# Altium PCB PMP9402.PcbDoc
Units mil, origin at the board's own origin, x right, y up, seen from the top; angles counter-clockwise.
Board outline 2250.03 x 802.03 mil, 2 copper layers (Top Layer, Bottom Layer), stack 62 mil thick; 47 components, 26 nets, 144 pads, 123 vias.
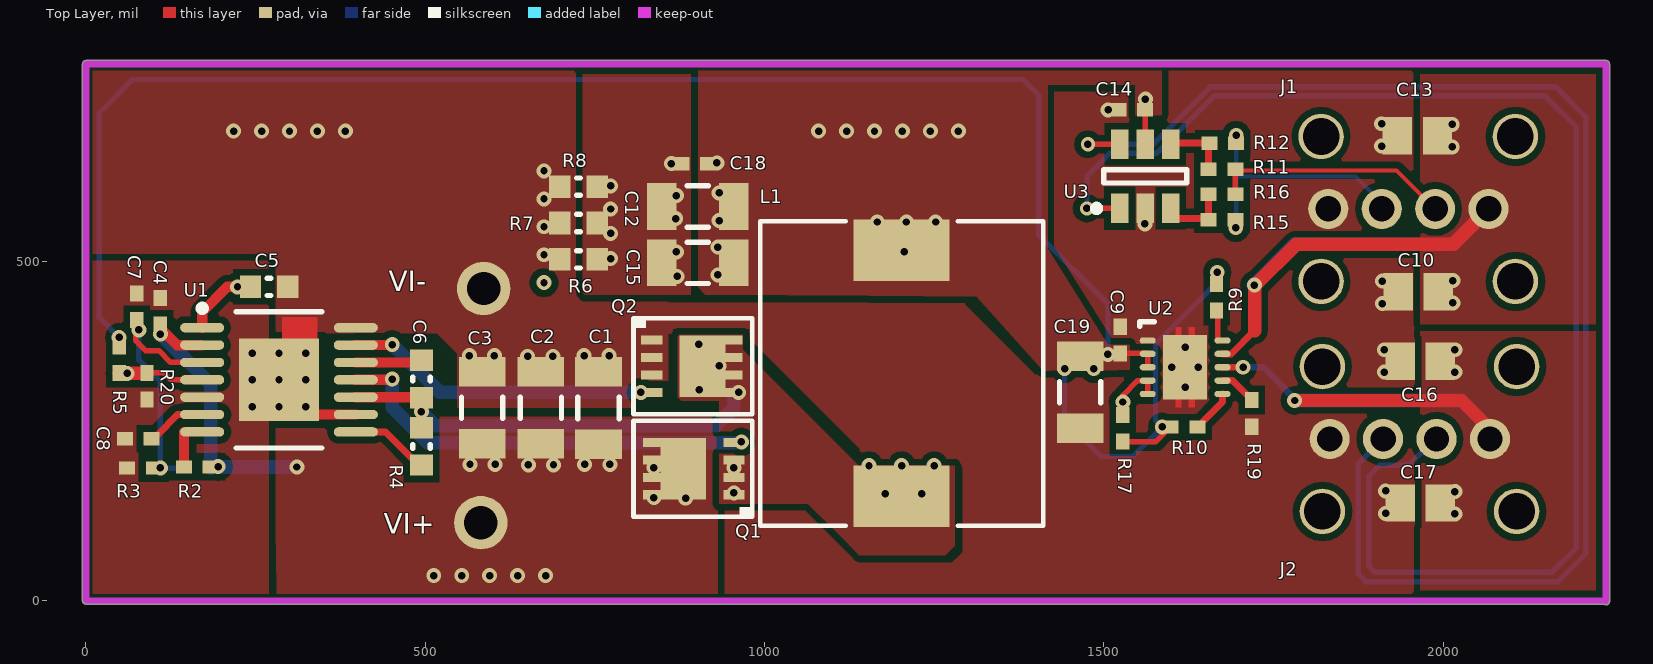
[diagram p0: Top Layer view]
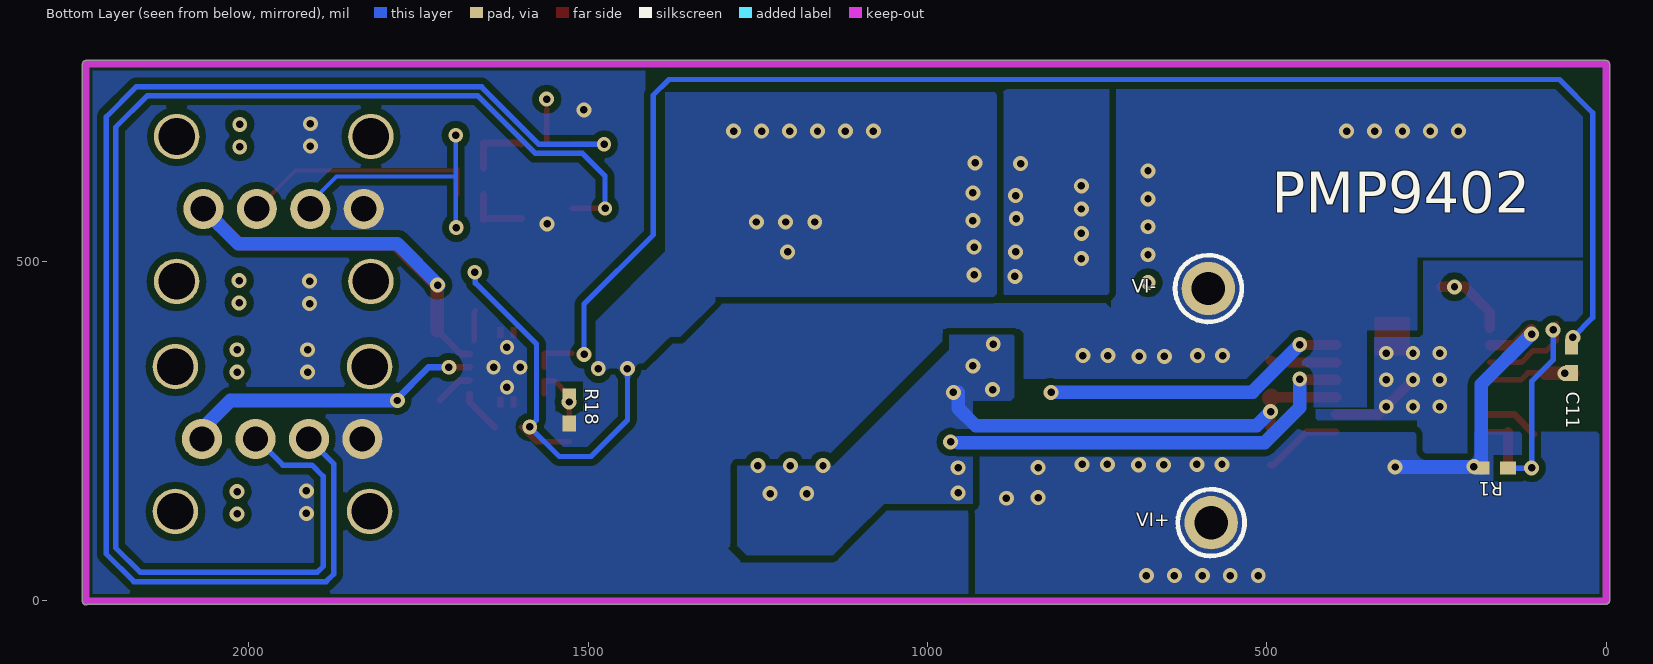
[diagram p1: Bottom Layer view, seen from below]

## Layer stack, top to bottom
Top Solder: solder mask 0.4, Solder Resist, Dk 3.5
Top Layer: signal copper 1.4
Dielectric1: core 59.2, FR-4, Dk 4.8
Bottom Layer: signal copper 1.4
Bottom Solder: solder mask 0.4, Solder Resist, Dk 3.5

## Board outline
0,-5.02 cw(c0,0) -5.01,0 -5.01,791 cw(c0,791) 0,796.01 2240,796.01 cw(c2240,791) 2245.02,791 cw(c2240,791) 2244.99,790.5 cw(c2240,790) 2245.02,790 2245.02,-1 cw(c2240,-1) 2236.99,-5.02

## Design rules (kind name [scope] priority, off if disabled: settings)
AcuteAngle [All] p1: minimum=4.50000000000000E+0001 checktracksonly=FALSE
AssemblyTestPointUsage [All] p1: valid=2
Clearance Clearance_BoardEdge_MountingHoles [OnCopper and InComponentClass('Mounting Holes') vs IsKeepOut] p1: gap=10
Clearance Clearance_BoardEdge_Poly [OnCopper and InPoly vs IsKeepOut] p2: gap=5
Clearance Clearance_BoardEdge [OnCopper and Not InComponentClass('Logo') and not InComponentClass('FiducialMark') and not InRegion(1000,500,4000,800) and Not IsKeepout vs IsKeepOut] p3: gap=10
Clearance Clearance_Poly [InPolygon] p4: gap=10
Clearance [All] p5: gap=5
ComponentClearance [All] p1: gap=0 collisioncheckmode=3 verticalgap=0 showdistances=FALSE
DiffPairsRouting [All] p1: maxlimit=100 minlimit=10 mostfreqgap=10 toplayer_minwidth=15 toplayer_maxwidth=15 toplayer_prefwidth=15 bottomlayer_minwidth=15 bottomlayer_maxwidth=15 bottomlayer_prefwidth=15 maxuncoupledlength=1000
FabricationTestPointUsage TestPointUsage [All] p1: valid=2 allowmultiple=FALSE
FabricationTestpoint Testpoint [All] p1: side=3 testpointundercomponent=TRUE minsize=40 maxsize=100 preferedsize=60 minholesize=0 maxholesize=40 preferedholesize=32 testpointgrid=1 allowsidetop=TRUE allowsidebottom=TRUE usegrid=TRUE gridtolerance=0.01
FanoutControl Fanout_LCC [IsLCC] p1: bgadir=Out bgaviamode=Centered fanoutstyle=Auto fanoutdirection=Alternating viagrid=1 // Fanout_LCC (Default Rule)
FanoutControl Fanout_BGA [IsBGA] p2: bgadir=Out bgaviamode=Centered fanoutstyle=Auto fanoutdirection=Alternating viagrid=1 // Fanout_BGA (Default Rule)
FanoutControl Fanout_Default [All] p4: bgadir=Out bgaviamode=Centered fanoutstyle=Auto fanoutdirection=Alternating viagrid=1 // Fanout_Default (Default Rule)
FanoutControl Fanout_Small [(CompPinCount < 5)] p5: bgadir=Out bgaviamode=Centered fanoutstyle=Auto fanoutdirection=OutThenIn viagrid=1 // Fanout_Small (Default Rule)
Height [All] p1: minheight=10 maxheight=1000 prefheight=500
HoleSize [All] p1: absolutevalues=TRUE maxlimit=251 minlimit=8 maxpercent=80.000 minpercent=20.000
HoleToHoleClearance [All] p1: gap=5 allowstackedmicrovias=TRUE
MinimumAnnularRing MinimumAnnularRing_ThermalPadVias [IsVia and InAnyComponent] p1: minimumring=2.5
MinimumAnnularRing [All] p2: minimumring=2.5
MinimumSolderMaskSliver MinimumSolderMaskSliver_Logo [InComponentClass('Logo') vs InComponentClass('Logo')] p1: minsoldermaskwidth=0.2
MinimumSolderMaskSliver [All] p2: minsoldermaskwidth=2
PlaneClearance [All] p1: clearance=5
PlaneConnect [All] p1: planeconnectstyle=Direct reliefexpansion=10 reliefentries=4 reliefconductorwidth=10 reliefairgap=10
PolygonConnect [All] p1: connectstyle=Direct reliefconductorwidth=10 reliefentries=4 polygonreliefangle="90 Angle" airgapwidth=10
RoutingVias ThermalPadVias [IsVia and InAnyComponent] p1: holewidth=11 width=21 viastyle="Through Hole" minholewidth=8 minwidth=20 maxholewidth=12.99 maxwidth=23.62
RoutingVias [All] p2: holewidth=11 width=21 viastyle="Through Hole" minholewidth=10 minwidth=21 maxholewidth=40 maxwidth=65
SMDToCorner [All] p1: distance=30000
SilkToSilkClearance [All] p1: silktosilkclearance=2
SilkToSolderMaskClearance SilkscreenOverComponentPads [IsPad] p1: minsilkscreentomaskgap=5 clearancetoexposedcopper=TRUE
SolderMaskExpansion [All] p1: expansion=1.97
UnpouredPolygon [All] p1: allowunpoured=FALSE
Width [All] p1: maxlimit=100 minlimit=6 preferedwidth=10 checkconnectedcopper=TRUE
12 further rules are at their usual default settings.

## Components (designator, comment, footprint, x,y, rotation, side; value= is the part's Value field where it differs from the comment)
C1 "GRM31CR71H475KA12L" 1206L 755.38,283.95 r90 top
C2 "GRM31CR71H475KA12L" 1206L 670.38,284.17 r90 top
C3 "GRM31CR71H475KA12L" 1206L 583.87,284.17 r90 top
C4 "C1005X7R1H104K050BB" 0402L 109.38,426.49 r90 top
C5 "GRM188R61C475KAAJ" 0603L 270.03,462.49 r0 top
C6 "GRM188R71E474KA12D" 0603L 494.38,326.49 r270 top
C7 "C1005X7R1H104K050BB" 0402L 75,433 r90 top
C8 "C1005X7R1H104K050BB" 0402L 77.18,238.49 r180 top
C9 "C1005X7R1H104K050BB" 0402L 1524,384 r90 top
C10 "JMK212BJ226KG-T" 0805L 1963,455 r180 top
C11 "C1005C0G1E821J" 0402L 51,355 r270 bottom
C12 "JMK316BJ107ML-T" 1206L 901.38,580.8 r180 top
C13 "JMK212BJ226KG-T" 0805L 1962,685 r180 top
C14 "C1005X7R1H104K050BB" 0402L 1541,723.32 r180 top
C15 "JMK316BJ107ML-T" 1206L 901.38,497.8 r180 top
C16 "JMK212BJ226KG-T" 0805L 1966,353 r180 top
C17 "JMK212BJ226KG-T" 0805L 1966,144 r180 top
C18 "C1005X7R1H104K050BB" 0402L 897,643.8 r180 top
C19 "JMK316BJ107ML-T" 1206L 1465,307 r270 top
J1 "PartNumber" 614004134726 1820,684 r180 top
J2 "614 004 134 726" 614004134726 1822,345 r180 top locked
L1 "7443331000" WE-HCC-10X9 1202,335 r90 top
Q1 "BSZ123N08NS3 G" PG-TSDSON-8 894.38,194.49 r180 top
Q2 "BSZ123N08NS3 G" PG-TSDSON-8 894.38,345.49 r0 top
R1 "CRCW04020000Z0ED" 0402L 164.2,195.49 r0 bottom
R2 "CRCW0402154KFKED" 0402L 164.2,197.12 r0 top
R3 "CRCW04020000Z0ED" 0402L 80.38,195.49 r0 top
R4 "CRCW06031K20JNEA" 0603L 494.38,227.49 r90 top
R5 "CRCW040275K0JNED" 0402L 49,355 r90 top
R6 "CRCW06030000Z0EA" 0603L 726,503 r0 top
R7 "CRCW06030000Z0EA" 0603L 726,556.5 r0 top
R8 "CRCW06030000Z0EA" 0603L 726,610 r0 top
R9 "CRCW040210K0FKED" 0402L 1666,447 r270 top
R10 "CRCW040210K0FKED" 0402L 1618,256 r0 top
R11 "CRCW04020000Z0ED" 0402L 1674,636 r180 top
R12 "CRCW04020000Z0ED" 0402L 1675,674 r180 top
R15 "CRCW04020000Z0ED" 0402L 1674,561.31 r0 top
R16 "CRCW04020000Z0ED" 0402L 1674,598.98 r0 top
R17 "CRCW040210K0FKED" 0402L 1528,254 r270 top
R18 "CRCW040210K0FKED" 0402L 1528,281 r90 bottom
R19 "CRCW040220K0FKED" 0402L 1718,276 r90 top
R20 "CRCW040210K0FKED" 0402L 90,316 r90 top
U1 "LM3150MH" MXA14A_N 284.57,325.49 r0 top locked (schematic designator U?)
U2 "TPS2561ADRC" DRC0010A 1619.66,344 r0 top locked
U3 "TPS2513DBV" DBV0006A_N 1561,625.32 r90 top
VI+ "Suggest using a net name here" Mill-Max_3125-2 582,115 r270 bottom
VI- "Suggest using a net name here" Mill-Max_3125-2 586,460 r270 bottom

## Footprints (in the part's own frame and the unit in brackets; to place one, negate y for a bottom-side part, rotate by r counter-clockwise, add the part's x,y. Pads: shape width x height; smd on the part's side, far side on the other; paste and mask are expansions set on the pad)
0402L [mm] "0402 from SM-752 data"
  rect 0.6x0.5 smd: 1(-0.5,0) 2(0.5,0)
  body extent -0.55,-0.3 0.55,0.3, height 0.6
0603L [mm] "0603 from SM-752 data"
  rect 0.8x0.85 smd: 1(-0.7,0) 2(0.7,0)
  silkscreen extent -0.07,-0.33 0.07,0.33, body extent -0.87,-0.47 0.87,0.47, height 0.85
0805L [mm] "0805 from SM-752 data"
  rect 1.1x1.4 smd: 1(-0.75,0) 2(0.75,0)
  body extent -1.1,-0.72 1.1,0.72, height 1.1
1206L [mm] "1206 from SM-752 data"
  rect 1.1x1.75 smd: 1(-1.35,0) 2(1.35,0)
  silkscreen extent -0.4,-0.77 0.4,0.77, body extent -1.7,-0.9 1.7,0.9, height 1.35
614004134726 [mm]
  round 1.7 hole 1.37: 0(-7.27,0) 0(-7.27,5.42) 0(0,5.42) 0(0,0)
  round 1.5 hole 0.95: 1(-6.27,2.71) 2(-2.27,2.71) 3(-4.27,2.71) 4(-0.27,2.71)
  body extent -18.68,-0.72 0.57,6.3, height 2.3
DBV0006A_N [mm] "SOT23, 6-Leads, Body 2.9x1.6mm, Pitch 0.95mm, Lead Span 2.8mm, IPC Medium Density"
  rect 1.1x0.65 smd: 1(-1.2,0.95) 2(-1.2,0) 3(-1.2,-0.95) 4(1.2,-0.95) 5(1.2,0) 6(1.2,0.95)
  silkscreen extent -1.32,-1.55 0.25,1.95, body extent -1.42,-1.46 1.42,1.46, height 1.11
DRC0010A [mm] "SON, 10-Leads, Body 3x3mm, Pitch 0.5mm, Thermal Pad 2.4x1.65mm, TI Recommended"
  oval 0.6x0.24 smd: 1(-1.4,1) 2(-1.4,0.5) 3(-1.4,0) 4(-1.4,-0.5) 5(-1.4,-1) 6(1.4,-1) 7(1.4,-0.5) 8(1.4,0) 9(1.4,0.5) 10(1.4,1)
  rect 1.65x2.4 smd paste-0.825: 11(0,0)
  Top Layer region: 0.135,-1.5 0.365,-1.5 0.365,-1.1 0.135,-1.1
  Top Layer region: -0.135,-1.1 -0.365,-1.1 -0.365,-1.5 -0.135,-1.5
  Top Layer region: -0.135,1.5 -0.365,1.5 -0.365,1.1 -0.135,1.1
  Top Layer region: 0.135,1.1 0.365,1.1 0.365,1.5 0.135,1.5
  silkscreen extent -1.7,1.54 -1.15,1.7, body extent -1.55,-1.55 1.55,1.55, height 1.01
Mill-Max_3125-2 [mm] "Mill-Max_3125"
  round 2 hole 1.25: 1(0,0)
  silkscreen extent -1.25,-1.25 1.25,1.25, body extent -0.89,-0.9 0.92,0.9, height 8.14
MXA14A_N [mm] "TSOP, 14-Leads, Body 5x4.4mm, Pitch 0.65mm, Exposed Pad, IPC Medium Density"
  oval 1.65x0.35 smd: 1(-2.875,1.95) 2(-2.875,1.3) 3(-2.875,0.65) 4(-2.875,0) 5(-2.875,-0.65) 6(-2.875,-1.3) 7(-2.875,-1.95) 8(2.875,-1.95) 9(2.875,-1.3) 10(2.875,-0.65) 11(2.875,0) 12(2.875,0.65) 13(2.875,1.3) 14(2.875,1.95)
  rect 3x3.1 smd: 15(0,0)
  silkscreen extent -3,-2.55 1.6,2.8, body extent -2.25,-2.55 2.25,2.55, height 1.1
PG-TSDSON-8 [mm] "Infineon recommended land pattern"
  rect 0.8x0.34 smd: 1(-1.538,0.975) 2(-1.538,0.325) 3(-1.538,-0.325) 4(-1.538,-0.975)
  rect 0.65x0.34 smd: 5(1.538,-0.975) 6(1.538,-0.325) 7(1.538,0.325) 8(1.538,0.975)
  rect 1.71x2.29 smd: 9(0.358,0)
  silkscreen extent -2.22,-1.8 2.22,1.8, body extent -1.7,-1.7 1.7,1.7, height 1.1
WE-HCC-10X9 [mm] "WERTH"
  rect 2.3x3.6 smd: 1(-4.6,0) 2(4.6,0)
  silkscreen extent -5.7,-5.3 5.7,5.3, body extent -5.12,-5 5.13,5, height 9.87

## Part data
C1 C2 C3: "CAP, CERM, 4.7uF, 50V, +/-10%, X7R, 1206"
C4 C7 C8 C9 C14 C18: "CAP, CERM, 0.1uF, 50V, +/-10%, X7R, 0402"
C5: "CAP, CERM, 4.7uF, 16V, +/-10%, X5R, 0603"
C6: "CAP, CERM, 0.47uF, 25V, +/-10%, X7R, 0603"
C10 C13 C16 C17: "CAP, CERM, 22uF, 6.3V, +/-10%, X5R, 0805"
C11: "CAP, CERM, 820pF, 25V, +/-5%, C0G/NP0, 0402"
C12 C15 C19: "CAP, CERM, 100uF, 6.3V, +/-20%, X5R, 1206"
J1: library part "614 004 134 726"
L1: "Inductor, Shielded Drum Core, Ferrite, 10uH, 8A, 0.0207 ohm, SMD"
Q1 Q2: "MOSFET, N-CH, 80V, 40A, PG-TSDSON-8"
R1 R3 R11 R12 R15 R16: "RES, 0 ohm, 5%, 0.063W, 0402"
R2: "RES, 154k ohm, 1%, 0.063W, 0402"
R4: "RES, 1.2k ohm, 5%, 0.1W, 0603"
R5: "RES, 75k ohm, 5%, 0.063W, 0402"
R6 R7 R8: "RES, 0 ohm, 5%, 0.1W, 0603"
R9 R10 R17 R18 R20: "RES, 10.0k ohm, 1%, 0.063W, 0402"
R19: "RES, 20.0k ohm, 1%, 0.063W, 0402"
U1: "SIMPLE SWITCHER® CONTROLLER, 42V Synchronous Step-Down, 14-pin TSSOP-EP"
U2: "DUAL CHANNEL PRECISION ADJUSTABLE CURRENT-LIMITED POWER SWITCHES, DRC0010A"
U3: "DUAL CHANNEL AUTO DETECT USB CHARGING CONTROLLER, DBV0006A"
VI+ VI-: library part 3125-2-00-34-00-00-08-0, "PCB Pin, TH"

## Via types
v1: diameter 22, hole 11, Top Layer to Bottom Layer, tented both sides, 108 vias
v2: diameter 21, hole 11, Top Layer to Bottom Layer, tented both sides, 15 vias

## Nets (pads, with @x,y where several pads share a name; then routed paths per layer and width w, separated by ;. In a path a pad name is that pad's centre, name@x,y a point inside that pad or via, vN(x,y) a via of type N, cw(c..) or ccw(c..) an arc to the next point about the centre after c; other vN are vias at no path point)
5VOUT: C9.1 C11.1 C12.1 C14.1 C15.1 C18.1 C19.1 L1.2 R5.2 R9.1 R10.1 R17.2 U2.2 U2.3 U3.5 | length 2901.8
  Top Layer w8: C9.1 1563.91,364.32 U2.2 U2.3 ; R17.2 1576.63,234.31 R10.1 ; C14.1 1561,723 U3.5
  Bottom Layer w8: v1(49,388) 20,417 20,719 69,768 1381,768 1404,745 1404,539 1506,437 v1(1506,363) ; v1(1442,342) 1442,266 1495.5,212.5 1542.5,212.5 v1(1586,256) 1576,266 1576,378 1666,468 1666,483 v1(1667,484)
  other v1: 1485,342 931.18,480.01 1206,514 931.18,521.01 1166,558 1209,558 1252,558 933.18,560.01 933.18,601.01 929.8,645.01 1079.6,692 1120.8,692 1162,692 1203.2,692 1244.4,692 1285.6,692 1561,739
BST: C6.1 U1.12 | length 97.9
  Top Layer w15: U1.12 491.41,351.08 C6.1
DM1+: J2.3 U3.1 | length 2084.6
  Top Layer w8: v2(1475.07,578.07) U3.1
  Bottom Layer w8: v2(1475.07,578.07) 1475.07,625.94 1508.69,659.56 1577.94,659.56 1662.38,744 2149.78,744 2196,697.78 2196,78 2160,42 1899,42 1890.26,50.74 1890.26,183.26 1906.78,199.78 1949.78,199.78 1988.31,238.31 J2.3
DM1-: J2.2 U3.6 | length 2048.7
  Top Layer w8: v2(1476.44,672.56) U3.6
  Bottom Layer w8: v2(1476.44,672.56) 1572.56,672.56 1657,757 2166,757 2210,713 2210,69 2169.15,28.15 1885.85,28.15 1875,39 1875,201.94 J2.2
DM2+: J1.2 R12.1 R15.2 | length 375.9
  Bottom Layer w6: v1(1694.24,549.8) 1695,550.55 1695,625 ; v1(1695,685.81) 1695,625 ; J1.2 1909.37,586.63 1871,625 1695,625
DM2-: J1.3 R11.1 R16.2 | length 354.9
  Top Layer w6: R11.1@1693.69,634 1931.42,634 J1.3
  Top Layer w8: R16.2 1693.69,634 R11.1
DM2O+: R15.1 R16.1 U3.3 | length 92.2
  Top Layer w10: U3.3@1597.84,563.31 R15.1@1652.35,563.31 ; R15.1 R16.1
DM2O-: R11.2 R12.2 U3.4 | length 94.3
  Top Layer w10: U3.4 1600.15,674.31 1654.32,674.31 R11.2@1654.32,636.65
EN: C7.1 R1.1 R3.2 U1.3 | length 387.2
  Top Layer w8: C7.1@73.38,407.8 73.38,383.17 88.06,368.49 107.38,368.49 124.79,351.08 U1.3
  Bottom Layer w8: v1(78,399) 78,355 109.81,323.19 v1(109.81,195.71) 110.03,195.49 R1.1
FB: C11.2 R5.1 R20.2 U1.4 | length 126.8
  Top Layer w8: R20.2@89.63,335.31 R20.2 115.31,335.69 125.51,325.49 U1.4
  Top Layer w20: R5.1 R20.2@89.63,335.31
  other v1: 60.81,335
GND: C1.2 C2.2 C3.2 C4.2 C5.2 C7.2 C8.2 C9.2 C10.2 C13.2 C14.2 C16.2 C17.2 C19.2 J1.4 J2.4 Q2.1 Q2.2 Q2.3 R3.1 R6.1 R7.1 R8.1 R18.1 R19.1 R20.1 U1.5 U1.9 U1.14 U1.15 U2.1 U2.11 U3.2 VI-.1 | length 134.4
  Top Layer w15: v2(284.57,325.49) 335.75,274.31 U1.9
  other v1: 1915.24,128.8 1915.24,161.8 1913.24,336.8 651,360 688,360 565,361 602,361 734,361 771,361 1913.24,369.8 1910.24,437.8 1910.24,470.8 675,509.8 675,551 1560.31,555.32 675,592.2 675,633.4 1909.24,669.8 217.6,692 258.8,692 300,692 341.2,692 382.4,692 1909.24,702.8 1506.31,723.32
  other v2: 245.2,286.12 284.57,286.12 323.94,286.12 1619.66,314.47 245.2,325.49 323.94,325.49 1599.98,344 1639.35,344 245.2,364.86 284.57,364.86 323.94,364.86 1619.66,373.53
HG: Q1.4 U1.11 | length 620.8
  Top Layer w15: U1.11 v1@450.38,325.49
  Top Layer w20: v1@450.38,325.49 v1(451.38,326.49)
  Bottom Layer w20: v1(451.38,326.49) 451.38,284.72 503.22,232.87 954.91,232.87
  other v1: 965.87,233.92
ILIM: R4.1 U1.8 | length 116.8
  Top Layer w10: U1.8 397.98,248.49 441.38,248.49 489.94,199.93 R4.1
ILIMU2: R19.2 U2.7 | length 55.3
  Top Layer w10: U2.7 1689.69,324.31 1718,296 R19.2
LG: Q2.4 U1.13 | length 449.2
  Top Layer w15: U1.13 v1@450.56,376.67
  Top Layer w20: v1@450.56,376.67 v1(451.38,377.49)
  Bottom Layer w20: v1(451.38,377.49) 520.87,308 ; 520.87,306.92 v1(817.87,306.92)
NetC12_2: C12.2 C15.2 C18.2 R6.2 R7.2 R8.2
  other v1: 871.18,478.01 773.24,504.17 870.18,514.01 773.24,541.17 869.18,563.01 773.24,577.17 870.18,597.01 773.24,611.17 862.8,644.01
NetR9_2: R9.2 U2.10 | length 45.1
  Top Layer w8: R9.2 1668,425.31 U2.10@1668,383
NetR10_2: R10.2 U2.6 | length 64
  Top Layer w10: R10.2 1674.78,293.09 U2.6
NetR17_1: R17.1 R18.2 U2.4 U2.5 | length 94.2
  Top Layer w8: R17.1 v1(1528,292.81) 1528,302.65 1549.66,324.31 U2.4 U2.5
OUT1: C10.1 C13.1 J1.1 U2.9 | length 912.6
  Top Layer w10: U2.9 1687.68,363.68 1722,398
  Top Layer w20: 1722,398 1722,464 1783,525 2014.54,525 J1.1
  Bottom Layer w20: v1@1720,465 1781,526 2015.54,526 J1.1
  other v1: 2014.24,438.8 1721.69,465 2014.24,471.8 2013.24,668.8 2013.24,701.8
OUT2: C16.1 C17.1 J2.1 U2.8 | length 762.7
  Top Layer w10: U2.8 v1(1705,344)
  Top Layer w19: v1@1784,295 2027,295 2068.85,253.15 J2.1
  Bottom Layer w10: v1(1705,344) 1735,344 v1@1784,295
  Bottom Layer w20: v1@1784,295 2027,295 2066.69,255.31 J2.1@2066.69,238.31
  other v1: 2017.24,127.8 2017.24,160.8 1781,295 2017.24,336.8 2017.24,369.8
RON: R2.1 U1.7 | length 78.5
  Top Layer w8: U1.7@144.51,248.72 U1.7
  Top Layer w15: R2.1 U1.7@144.51,248.72
SS: C8.1 U1.6 | length 77.4
  Top Layer w10: C8.1@106.06,245.17 135.2,274.31 U1.6
SW: C6.2 L1.1 Q1.1 Q1.2 Q1.3 Q2.5 Q2.6 Q2.7 Q2.8 Q2.9 R4.2 U1.10 | length 644
  Top Layer w15: U1.10 C6.2@493.41,299.9 ; R4.2 v1(494.38,278.49) C6.2
  Top Layer w25: C6.2@493.41,299.9 C6.2
  Bottom Layer w20: v1(494.38,278.49) 514.99,257.87 929,257.87 954.91,283.78 v1@954.91,307.1
  other v1: 1177.87,157.92 1231.87,157.92 954.87,158.92 954.87,195.92 1153.87,198.92 1201.87,198.92 1249.87,198.92 961.87,306.92 904,311 933,346 903,378
VCC: C5.1 U1.1 | length 111.1
  Top Layer w15: U1.1 171.38,425.49 208.38,462.49 v1(223.38,462.49) C5.1
  Bottom Layer w15: v1(223.38,462.49) v1@224.38,461.49
VIN: C1.1 C2.1 C3.1 C4.1 Q1.5 Q1.6 Q1.7 Q1.8 Q1.9 R1.2 R2.2 U1.2 VI+.1 | length 424.7
  Top Layer w10: U1.2@171.2,376.49 U1.2
  Top Layer w15: C4.1@110.38,400.49 134.38,376.49 U1.2@171.2,376.49
  Bottom Layer w20: v1(109.87,392.92) 183.88,318.9 R1.2 ; R1.2@185.4,197 v1(311,197)
  other v1: 512.6,37 553.8,37 595,37 636.2,37 677.4,37 883.8,151 837,152 837,196 194.81,197.71 652,200 689,200 566,201 603,201 735,201 772,201
pads on no net: J1.0 J2.0
copper on no net:
  other v1: 675,468.6

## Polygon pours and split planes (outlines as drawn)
GND on Top Layer "L1" (solid, remove dead copper, pour order 27): 0,500 1,501 269.8,501.33 269.8,0 0,0
GND on Top Layer "L1" (solid, remove dead copper, pour order 29): 1741,791 1964,791 1964,321.5 1966.41,319.09 1966.41,2.41 1960,-4 1419,-4 1419,788 1743,788
GND on Top Layer "Top Layer-No Net 7" (solid, remove dead copper, pour order 28): 847,439 1295,439 1295,436.85 1398.84,333.01 1398.85,333 1538,333 1538,-3 1536,-5 934,-5 934,126 942,134 945,137 1056,137 1057,137 1127,67 1138,56 1194,56 1276,56 1288,68 1292,72 1292,194 1292,196 1285,203 1279,209 1140,209 1140,224 966,398 961,393 846,393 846,438 847,439
5VOUT on Top Layer "Top Layer-No Net 3" (solid, remove dead copper, pour order 22): 902,791 902,463.01 901.38,462.39 912.77,451 1313,448 1410.66,339 1537.78,340.03 1537.78,377 1506,377 1417,519 1417,760 1546,760 1546,715 1585,715 1585,791
VIN on Top Layer "Top Layer-No Net 6" (solid, remove dead copper, pour order 26): 925,271 931,265 931,0 281,0 281,20 278,271
GND on Top Layer "Top Layer-No Net 5" (solid, remove dead copper, pour order 24): 280,791 -2,789 -2,506 280,506 280,394 517,394 547,364 547,284.17 858,284.17 858,451 735,451 730,456 730,791
NetC12_2 on Top Layer "Top Layer-No Net 4" (solid, remove dead copper, pour order 23): 733,790 888,790 891,793 891,451 735,451 732,454 732,791 888,791 890,789
OUT2 on Top Layer "Top Layer-No Net 2" (solid, remove dead copper, pour order 21): 1966.41,407 2236,407 2237,408 2240,405 2240,0 1967,0 1966.41,0.59 1966.41,407
OUT1 on Top Layer "Top Layer-No Net 1" (solid, remove dead copper, pour order 20): 1966,793 1966,408 1965,407 2240,407 2240,790 2237,793 1966,793
SW on Top Layer "Top Layer-No Net" (solid, remove dead copper, pour order 19): 873,393 874,392 968,392 968,370 1136,202 1139,199 1280,199 1280,83 1281,82 1266,67 1139,67 1139,68 1110,97 1064,143 991,143 932,143 933,144 933,295 877,295 873,299 872,300 872,392
5VOUT on Bottom Layer "Bottom Layer-No Net 1" (solid, remove dead copper, pour order 31): 901,749 1386,749 1386,515 1489,412 1489,328.5 1424.5,328.5 1313,440 1313,448 902,448 898,452 898,746
VIN on Bottom Layer "Bvin" (solid, remove dead copper, pour order 25): 925,272 931,266 931,1 281,1 0.21,1 -0.88,248.71 441.38,248.49 505,271
GND on Bottom Layer "Bottom Layer-No Net 3" (solid, remove dead copper, pour order 34): 31,501 31.35,500.65 269.8,500.65 269.8,392.9 272.62,390.08 274.7,388 342,388 342,283 343,282 428,282 428,269 427,268 425,266 278,266 278,214 277,213 197,213 197,326 186,337 110.87,412.13 55.16,412.13 37.87,412.13 31,419 34.27,422.27 34.27,506
GND on Bottom Layer "PGND" (solid, remove dead copper, pour order 33): 0,793 718,793 729,782 729,430 736.94,437.94 1316.28,437.94 1427,327.22 1427,-2 1426,-3 1422,1 940,1 940,130 937.2,132.8 1061.2,132.8 1138,56 1276,56 1276,59 1294,77 1287.21,83.79 1287.21,206.21 1154.12,206.21 977.7,382.63 977.7,400.57 864.79,400.57 858,393.77 858,326.7 530.3,326.7 464,393 464,285 353,285 353,398 278.49,398.35 278.49,506 3,506 -1,510 0,511
NetC12_2 on Bottom Layer "Bottom Layer-No Net 2" (solid, remove dead copper, pour order 32): 734,772 887.29,772 891,775.71 891,451 735,451 732,454 732,775.71
SW on Bottom Layer "B SW" (solid, remove dead copper, pour order 18): 873,393 874,392 968,392 968,370 1136,202 1139,199 1280,199 1280,83 1281,82 1266,67 1139,67 1139,68 1110,97 1064,143 991,143 932,143 933,144 933,295 877,295 873,299 872,300 872,392
GND on Bottom Layer "Bottom Layer-No Net" (solid, remove dead copper, pour order 30): 1418,793 2237,793 2237,0 2235,-2 1416,-2 1416,793

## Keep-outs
Keep-Out Layer:
  lines w10: 2240,-1 2240,790 ; 2240,0 0,0 0,791 2240,791 ; 11,3080 cw(c16,3080) 16,3085 ; 11,3080 cw(c16,3080) 16,3085 ; 11,3080 cw(c16,3080) 16,3085 ; 11,3080 cw(c16,3080) 16,3085 ; 11,3080 cw(c16,3080) 16,3085 ; 11,3080 cw(c16,3080) 16,3085
  text ".Layer_Name" at 593,-1228.49 h60

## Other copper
Top Layer:
  rectangle net GND: 289,361 341,418
  text ".Layer_Name" at 593,-1228.49 h60
Bottom Layer:
  text ".Layer_Name" at 593,-1228.49 h60

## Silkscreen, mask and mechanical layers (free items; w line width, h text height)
Top Overlay:
  text "VI-" at 446,456 h30
  text "VI+" at 439,99 h30
  text ".Layer_Name" at 593,-1228.49 h20
Bottom Overlay:
  text "PMP9402" at 493,572 h60
  text ".Layer_Name" at 593,-1228.49 h60
Top Paste:
  text ".Layer_Name" at 593,-1228.49 h60
Bottom Paste:
  text ".Layer_Name" at 593,-1228.49 h60
Top Solder:
  text ".Layer_Name" at 593,-1228.49 h60
  text ".Layer_Name" at 593,-1228.49 h60
Bottom Solder:
  text ".Layer_Name" at 593,-1228.49 h60
Drill Guide:
  text ".Layer_Name" at 593,-1228.49 h60
M1 Board Outline:
  lines w15: 0,0 0,793 2237,793 2237,0 0,0
  text ".Layer_Name" at 593,-1228.49 h60
M2 Board Dimensions:
  rectangle: 15.5,-655.5 140.5,-530.5
  rectangle: 140.5,-780.5 515.5,-655.5
  lines w7: 15.5,-655.5 1015.5,-655.5 ; 140.5,-780.5 140.5,-530.5 ; 265.5,-780.5 265.5,-530.5 ; 515.5,-780.5 515.5,-530.5 ; 765.5,-780.5 765.5,-530.5 ; 15.5,-780.5 1015.5,-780.5 1015.5,-530.5 15.5,-530.5 15.5,-780.5
  lines w10: 15.5,-845.5 15.5,-825.5 ; 75.5,-855.5 15.5,-835.5 ; 75.5,-815.5 15.5,-835.5 ; 239.59,-835.5 15.5,-835.5 ; 791.42,-835.5 1015.5,-835.5 ; 955.5,-855.5 1015.5,-835.5 ; 955.5,-815.5 1015.5,-835.5 ; 1015.5,-845.5 1015.5,-825.5
  text "1000 (mil)" at 249.59,-871.49 h60
  text ".Layer_Name" at 593,-1228.49 h60
M3 3D STEP Top:
  text ".Layer_Name" at 593,-1228.49 h60
M4 3D STEP Bottom:
  text ".Layer_Name" at 593,-1228.49 h60
M5 Assembly Top:
  lines w10: -276,-1300.17 6324,-1300.17 ; -276,-1096.83 6326,-1096.83 ; -276,-893.5 -276,-1503.5 3729,-1503.5 6326,-1503.5 6326,-893.5 -275.5,-893.5 -275.5,-1503.5 1300,-1503.5 ; 2189,-1503.5 2189,-893.5 ; 3456,-1096.83 3456,-893.5 ; 4296,-1096.83 4296,-893.5 ; 4918,-1510 4918,-1307.17
  text "COMPONENTS MARKED 'DNP' SHOULD NOT BE POPULATED." at 1169.5,-688.5 h60
  text "ASSEMBLY VARIANT:" at 1169,-804 h60
  text ".VariantName" at 2205,-804 h60
  text "PCB VIEWED FROM TOP SIDE" at -212.5,-1025.67 h60
  text "BOARD #:" at 2264,-1025.67 h60
  text ".PRJ_Number" at 2809.5,-1025.67 h60
  text "REV:" at 3654,-1025.67 h60
  text ".PCB_Rev" at 3945.5,-1025.67 h60
  text "SVN REV:" at 4492,-1025.67 h60
  text ".VersionControl_RevNumber" at 4998,-1025.67 h60
  text "IGNORE ->" at -212.5,-1228.49 h60
  text "PLOT NAME =" at -212.5,-1434.34 h60
  text ".plot_File_Name" at 593,-1434.34 h60
  text "GENERATED    :" at 2266,-1434.34 h60
  text ".Print_Date" at 3135.5,-1434.34 h60
  text ".Print_Time" at 3864.5,-1434.34 h60
  text "TEXAS INSTRUMENTS" at 5129,-1434.34 h60
M6 Assembly Bottom:
  lines w10: -276.5,-1097.33 6325.5,-1097.33 ; -274.5,-1300.67 6325.5,-1300.67 ; 1131.5,-1510.5 1131.5,-1307.67 ; 1753.5,-1097.33 1753.5,-894 ; 2593.5,-1097.33 2593.5,-894 ; 3860.5,-1504 3860.5,-894 ; 4749.5,-1504 6325,-1504 6325,-894 -276.5,-894 -276.5,-1504 2320.5,-1504 6325.5,-1504 6325.5,-894
  text "COMPONENTS MARKED 'DNP' SHOULD NOT BE POPULATED." at 6118,-688 h60
  text ".VariantName" at 5074,-804 h60
  text "ASSEMBLY VARIANT:" at 6113,-804 h60
  text ".VersionControl_RevNumber" at 1051.5,-1026.17 h60
  text "SVN REV:" at 1557.5,-1026.17 h60
  text ".PCB_Rev" at 2104,-1026.17 h60
  text "REV:" at 2395.5,-1026.17 h60
  text ".PRJ_Number" at 3240,-1026.17 h60
  text "BOARD #:" at 3785.5,-1026.17 h60
  text "PCB VIEWED FROM BOTTOM SIDE" at 6262,-1026.17 h60
  text "IGNORE ->" at 2563.85,-1228.49 h60
  text "TEXAS INSTRUMENTS" at 920.5,-1434.84 h60
  text ".Print_Time" at 2185,-1434.84 h60
  text ".Print_Date" at 2914,-1434.84 h60
  text "GENERATED    :" at 3783.5,-1434.84 h60
  text ".plot_File_Name" at 5456.5,-1434.84 h60
  text "PLOT NAME =" at 6262,-1434.84 h60
M9 Title Sheet:
  drawing of 57 lines, arcs and shapes, not listed
  text "1" at 755.84,7666.5 h70
  text "2" at 3251.5,7666.5 h70
  text "3" at 5740.84,7666.5 h70
  text "4" at 8247.51,7666.5 h70
  text "5" at 10746.5,7666.5 h70
  text "6" at 13251.5,7666.5 h70
  text "A" at -400.5,6523.5 h70
  text "A" at 14399.5,6523.5 h70
  text "B" at -400.5,4143.5 h70
  text "B" at 14399.5,4143.5 h70
  text "C" at -400.5,1768.5 h70
  text "C" at 14399.5,1768.5 h70
  text "PROJECT TITLE:" at 11359.5,-92.5 h45
  text ".PRJ_Title" at 11409.5,-225.83 h70
  text "DESIGNED FOR:" at 11359.5,-393.5 h45
  text ".PRJ_Customer" at 11409.5,-533.5 h70
  text "D" at -400.5,-601.5 h70
  text "D" at 14399.5,-601.5 h70
  text "FILE NAME:" at 11359.5,-693.5 h45
  text ".PCB_File_Name_No_Path" at 11409.5,-813.5 h70
  text "Texas Instruments (TI) and/or its licensors do not warrant the accuracy or completeness of this specification" at 6390,-975.34 h45
  text "ENGINEER:" at 11359.5,-983.5 h45
  text "LAYOUT BY:" at 12864.5,-983.5 h45
  text "or any information contained therein. TI and/or its licensors do not warrant that this design will meet" at 6345.02,-1088 h45
  text ".PRJ_Engineer" at 11409.5,-1138.49 h70
  text ".PCB_Layout" at 12915,-1138.49 h70
  text "the specifications, will be suitable for your application or fit for any particular purpose, or will operate in" at 6345.02,-1200.67 h45
  text ".Layer_Name" at 593,-1228.49 h60
  text "ALTIUM DESIGNER VERSION:" at 12864.5,-1293.5 h45
  text "an implementation. TI and/or its licensors do not warrant that the design is production worthy. You should" at 6345.02,-1313.33 h45
  text "completely validate and test your design implementation to confirm the system functionality for your application." at 6390,-1426 h45
  text ".print_Scale" at 11409.5,-1426.83 h70
  text ".Application_BuildNumber" at 12915,-1426.83 h70
  text "1" at 755.84,-1633.5 h70
  text "2" at 3251.5,-1633.5 h70
  text "3" at 5740.84,-1633.5 h70
  text "4" at 8247.51,-1633.5 h70
  text "5" at 10746.5,-1633.5 h70
  text "6" at 13251.5,-1633.5 h70
M10 Fab Notes:
  drawing of 212 lines, arcs and shapes, not listed
  text "DESIGN INFORMATION" at 12397.02,6440 h60
  text "(REFER ALSO ARRAY/PANEL PROFILING INFORMATION)" at 12035.46,6278.29 h60
  text "BOARD SIZE" at 11349.46,6274 h60
  text "793MIL" at 11811.78,6146.18 h60
  text "X" at 12317.46,6146.18 h60
  text "2240MIL" at 12548.78,6146.18 h60
  text "Number of Layers :" at 11752.46,5949 h60
  text "2" at 12847.27,5939 h60
  text "MIN. TRACK WIDTH:" at 11752.46,5810 h60
  text "8" at 12848.7,5810 h60
  text "MIL" at 13003.46,5810 h60
  text "MIN. CLEARANCE:" at 11752.46,5678 h60
  text "8" at 12848.7,5678 h60
  text "MIL" at 13003.46,5678 h60
  text "MIN. VIA PAD SIZE:" at 11752.46,5546 h60
  text "24" at 12818.71,5546 h60
  text "MIL" at 13003.46,5546 h60
  text "0.05mm (2MIL)" at 12447.46,5404.29 h60
  text "MINIMUM ANNULAR RING" at 11423.23,5400 h60
  text "EXTERNAL" at 13155.46,5400 h60
  text "PER" at 11623.23,5282 h60
  text "IPC-D-275 CLASS 2 LEVEL C" at 11843.23,5282 h60
  text "MIL, HOLES" at 13331.46,5169.71 h60
  text "+/-" at 12939,5169 h60
  text "+/-" at 13793,5169 h60
  text "REGISTRATION TOLERANCES:" at 11423.23,5164 h60
  text "METAL" at 12623,5164 h60
  text "5" at 13199.2,5164 h60
  text "3" at 14032.2,5164 h60
  text "MIL" at 14148.46,5164 h60
  text "MATERIAL:" at 11348.46,4954.54 h60
  text "FR-4 High Tg" at 12334.9,4814.21 h60
  text "FR-4" at 13776,4808 h60
  text "FR-408" at 11769.46,4805.64 h60
  text "X" at 12181.46,4805.64 h60
  text "X" at 13065.46,4805.64 h60
  text "OTHER" at 13257.46,4805.64 h60
  text "62 MIL (1.6mm) +/-10%" at 12089.56,4642.92 h60
  text "THICKNESS:" at 11423.23,4638.64 h60
  text "X" at 11961.4,4638.64 h60
  text "OTHER" at 13374.46,4638.64 h60
  text "TOLERANCE:" at 11423.23,4480.64 h60
  text "X" at 12262.54,4480.64 h60
  text "ANSI IPC-6012 TYPE 3 CLASS 2" at 12449.48,4480.64 h60
  text "OTHER +/-" at 12449.46,4324.64 h60
  text "BOW & TWIST:" at 11423.23,4167.64 h60
  text "X" at 12262.54,4167.64 h60
  text "ANSI IPC-6012 TYPE 3 CLASS 2" at 12449.48,4167.64 h60
  text "OTHER +/-" at 12449.46,4009.13 h60
  text "COPPER THICKNESS (FINISHED):" at 11348.46,3873.64 h60
  text "1.4MIL (1oz)" at 12228.46,3720.92 h60
  text "2MIL (1.4oz)" at 12995.46,3720.92 h60
  text "2.8MIL (2oz)" at 13722.46,3720.92 h60
  text "OUTER:" at 11705.46,3716.64 h60
  text "X" at 12100,3716 h60
  text "1.4MIL (1oz)" at 12228.46,3563.92 h60
  text "2.8MIL (2oz)" at 12995.46,3563.92 h60
  text "N/A" at 13722,3564.29 h60
  text "INNER SIGNAL:" at 11416.38,3559.64 h60
  text "X" at 12101.42,3559.64 h60
  text "DRILLING:" at 11348.46,3420.64 h60
  text "REFERENCE:" at 11423.23,3303.64 h60
  text "X" at 12071.46,3303.64 h60
  text "AS SHOWN" at 12258.46,3303.64 h60
  text "X" at 12972.46,3303.64 h60
  text "NC_DRILL FILES" at 13109.46,3303.64 h60
  text "PTH MIN COPPER THICKNESS:" at 11423.23,3145.64 h60
  text "X" at 12773.46,3145.64 h60
  text "1MIL" at 12910.46,3145.64 h60
  text "OTHER" at 13407.46,3145.64 h60
  text "BOARD FINISH:" at 11348.46,2986.64 h60
  text "SILKSCREEN:" at 11503.68,2868.64 h60
  text "X" at 12452.46,2868.64 h60
  text "TOP" at 12578.46,2868.64 h60
  text "X" at 12962.46,2868.64 h60
  text "BOTTOM" at 13089.46,2868.64 h60
  text "SILKSCREEN COLOR:" at 11503.68,2701.64 h60
  text "X" at 12451.42,2701.64 h60
  text "WHITE" at 12578.46,2701.64 h60
  text "OTHER" at 13089.46,2701.64 h60
  text "SOLDER RESIST COLOR:" at 11503.68,2531.64 h60
  text "X" at 12071.42,2372.44 h60
  text "GREEN" at 12198.46,2372.44 h60
  text "BLUE" at 12789.46,2372.44 h60
  text "OTHER" at 13327.46,2372.44 h60
  text "IMMERSION GOLD (ENIG)" at 12409.46,2183.92 h60
  text "ENEPIG" at 13747,2180.64 h60
  text "SURFACE FINISH:" at 11348.46,2179.64 h60
  text "HASL" at 13778.46,2032.64 h60
  text "IMM. TIN/SILVER OR EQUIV" at 11678,2022.64 h60
  text "OTHER" at 13109.46,2022.64 h60
  text "X" at 12920,2021 h60
  text "ARRAY/PANEL:" at 11348.46,1843.64 h60
  text "X" at 12218,1844 h60
  text "CUT AND TRIM PER MECH LAYER 1" at 12409.46,1839.35 h60
  text "N.C. ROUTE" at 12409.46,1687.64 h60
  text "V. SCORE" at 13275.46,1687.64 h60
  text "CERTIFICATION:" at 11348.46,1550.64 h60
  text "MATERIALS AND WORKMANSHIP FOR ALL PCBS" at 12073.46,1550.64 h60
  text "TO MEET OR EXCEED THE REQUIREMENTS OF:" at 12073.46,1452.64 h60
  text "X" at 11699.96,1316.13 h60
  text "ANSI IPC-A-600F CLASS ->" at 11838.96,1316.13 h60
  text "X" at 13478.02,1316.13 h60
  text "2" at 13596.96,1316.14 h60
  text "1" at 13281.96,1314.64 h60
  text "3" at 13950.96,1314.64 h60
  text "X" at 11702.02,1156.64 h60
  text "UL 94V-0" at 11838.96,1156.64 h60
  text "X" at 12514.02,1156.64 h60
  text "RoHS" at 12650.96,1156.64 h60
  text "OTHER" at 13295.37,1156.64 h60
  text "PER ORDER" at 13692.42,1156.64 h60
  text "ADDITIONAL REQUIREMENTS:" at 11348.46,1015.64 h60
  text "MICROSECTION:" at 11423.23,900.64 h60
  text "YES" at 12328.96,900.64 h60
  text "X" at 13652,745 h60
  text "REQUIRED" at 13190.46,744.49 h60
  text "BARE BOARD ELEC. TEST:" at 11423.23,741.64 h60
  text "NONE" at 12728.96,741.64 h60
  text "PER ORDER" at 13782.46,741.64 h60
  text "MANUFACTURER'S UL:" at 11423.23,584.64 h60
  text "RAIL" at 12588.96,580.35 h60
  text "METAL" at 13080.78,580.35 h60
  text "X" at 13456,580 h60
  text "SILK" at 13592.46,580.35 h60
  text ".Layer_Name" at 593,-1228.49 h60
M11 Gerber Information:
  lines w10: -276,-1300.17 6324,-1300.17 ; -276,-1096.83 6326,-1096.83 ; -276,-893.5 -276,-1503.5 3729,-1503.5 6326,-1503.5 6326,-893.5 -275.5,-893.5 -275.5,-1503.5 1300,-1503.5 ; 2189,-1503.5 2189,-893.5 ; 3456,-1096.83 3456,-893.5 ; 4296,-1096.83 4296,-893.5 ; 4918,-1510 4918,-1307.17
  text "ALL ARTWORK VIEWED FROM TOP SIDE" at -212.5,-1025.67 h60
  text "BOARD #:" at 2264,-1025.67 h60
  text ".PRJ_Number" at 2809.5,-1025.67 h60
  text "REV:" at 3654,-1025.67 h60
  text ".PCB_Rev" at 3945.5,-1025.67 h60
  text "SVN REV:" at 4492,-1025.67 h60
  text ".VersionControl_RevNumber" at 4998,-1025.67 h60
  text "LAYER NAME =" at -212.5,-1228.49 h60
  text "PLOT NAME =" at -212.5,-1434.34 h60
  text ".plot_File_Name" at 593,-1434.34 h60
  text "GENERATED    :" at 2266,-1434.34 h60
  text ".Print_Date" at 3135.5,-1434.34 h60
  text ".Print_Time" at 3864.5,-1434.34 h60
  text "TEXAS INSTRUMENTS" at 5129,-1434.34 h60
M12 Stackup:
  lines w6: 11376,7090 13926,7090 ; 11376,7194.4 13926,7194.4 ; 11316,6605 ccw(c11350,6605) 11350,6571 13952,6571 ccw(c13952,6605) 13986,6605 13986,7311 ccw(c13952,7311) 13952,7345 11350,7345 ccw(c11350,7311) 11316,7311 11316,6605
  text "The Stackup Legend below this is static." at 11621.5,7504.5 h60
  text "If you change the stackup, update the Legend." at 11631.5,7414.5 h60
  text "Layer Stack Up Detail for: Ref_Design.PcbDoc" at 11376,7227.1 h57
  text "Layer" at 11376,7155.4 h24
  text "Gerber" at 12271.81,7155.4 h24
  text "Copper" at 12835.33,7155.4 h24
  text "Dielectric" at 13438.04,7155.4 h24
  text "Name" at 11376,7107.4 h24
  text "Document" at 12271.81,7107.4 h24
  text "Thickness" at 12835.33,7107.4 h24
  text "Material" at 13438.04,7107.4 h24
  text "Top Solder Mask" at 11376,7014.44 h34
  text "(.GTS)" at 12271.81,7014.44 h34
  text "Solder Resist" at 13438.04,7014.44 h34
  text "Top Layer" at 11376,6917.69 h34
  text "(.GTL)" at 12271.81,6917.69 h34
  text "1.4mil" at 12835.33,6917.69 h34
  text "FR-4" at 13438.04,6869.31 h34
  text "Bottom Layer" at 11376,6820.94 h34
  text "(.GBL)" at 12271.81,6820.94 h34
  text "1.4mil" at 12835.33,6820.94 h34
  text "Bottom Solder Mask" at 11376,6724.19 h34
  text "(.GBS)" at 12271.81,6724.19 h34
  text "Solder Resist" at 13438.04,6724.19 h34
  text ".Layer_Name" at 593,-1228.49 h60
M13 Component Bodies Top:
  text ".Layer_Name" at 593,-1228.49 h60
M14 Component Bodies Bottom:
  text ".Layer_Name" at 593,-1228.49 h60
M15 Courtyards Top:
  text ".Layer_Name" at 593,-1228.49 h60
M16 Courtyards Bottom:
  text ".Layer_Name" at 593,-1228.49 h60
Drill Drawing:
  text ".Layer_Name" at 593,-1228.49 h60
  text ".legend" at 2922,-1263 h60
  text "Drill Table" at 3441,-1459 h60

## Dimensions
0,0 to 2240,0 on M2 Board Dimensions
0,0 to 30,793 on M2 Board Dimensions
